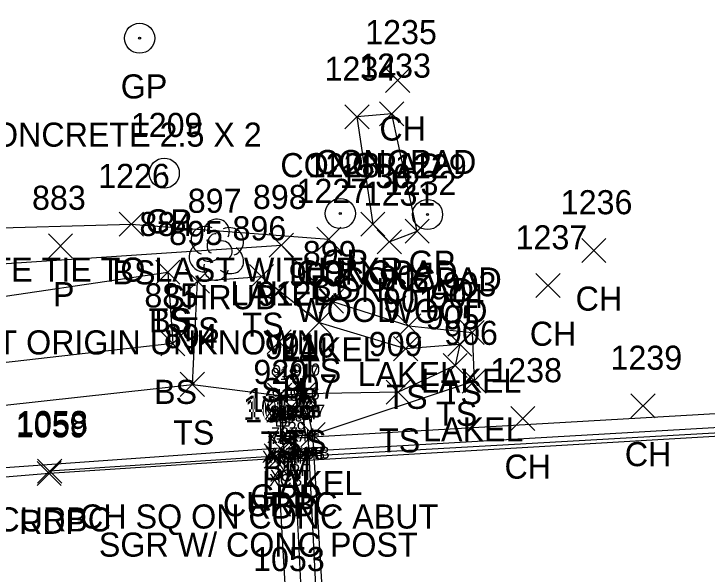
# Model space of a CAD drawing. Extents: x 1716490 to 1717645, y 888034 to 890004.
# Drawn here: x 1716855 to 1716912.5, y 888233.3 to 888279.7 of the extents above; entities that cross this region are included whole.
import ezdxf

# ---------------------------------------------------------------- set-up
doc = ezdxf.new("R2010")
doc.units = 0
for name, color, linetype in [('B_A', 7, 'Continuous'), ('B_I', 7, 'Continuous'), ('B_TIC', 7, 'Continuous'), ('BDC', 7, 'Continuous'), ('BF', 7, 'Continuous'), ('BR', 7, 'Continuous'), ('BSE', 7, 'Continuous'), ('BSUBM', 7, 'Continuous'), ('C_A', 7, 'Continuous'), ('C_C', 7, 'Continuous'), ('C_I', 7, 'Continuous'), ('CPBM', 7, 'Continuous'), ('D_A', 7, 'Continuous'), ('D_C', 7, 'Continuous'), ('D_I', 7, 'Continuous'), ('D_TIC', 7, 'Continuous'), ('L_A', 7, 'Continuous'), ('L_I', 7, 'Continuous'), ('L_TIC', 7, 'Continuous'), ('LAWE', 7, 'Continuous'), ('LELB', 7, 'Continuous'), ('LS', 7, 'Continuous'), ('LSH', 7, 'Continuous'), ('P_A', 7, 'Continuous'), ('P_I', 7, 'Continuous'), ('P_TIC', 7, 'Continuous'), ('PET', 7, 'Continuous'), ('R_A', 7, 'Continuous'), ('R_C', 7, 'Continuous'), ('R_I', 7, 'Continuous'), ('R_TIC', 7, 'Continuous'), ('RC', 7, 'Continuous'), ('RGP', 7, 'Continuous'), ('RGR', 7, 'Continuous')]:
    doc.layers.add(name, color=color, linetype=linetype)

msp = doc.modelspace()

# ---------------------------------------------------------------- linework, layer by layer
at = {"layer": 'B_TIC'}
for p, q in [((1716879.094, 888248.225), (1716879.169, 888248.225)), ((1716877.033, 888248.088), (1716877.108, 888248.088)), ((1716877.197, 888247.861), (1716877.272, 888247.861)), ((1716878.974, 888248.087), (1716879.049, 888248.087)), ((1716877.278, 888246.136), (1716877.354, 888246.136)), ((1716879.046, 888246.236), (1716879.121, 888246.236)), ((1716877.138, 888244.751), (1716877.214, 888244.751)), ((1716877.276, 888244.688), (1716877.351, 888244.688)), ((1716878.173, 888244.72), (1716878.249, 888244.72)), ((1716879.151, 888244.793), (1716879.226, 888244.793)), ((1716879.373, 888244.78), (1716879.449, 888244.78)), ((1716879.797, 888244.823), (1716879.873, 888244.823)), ((1716877.305, 888244.49), (1716877.38, 888244.49)), ((1716877.305, 888244.49), (1716877.38, 888244.49)), ((1716877.965, 888244.411), (1716878.041, 888244.411)), ((1716878.145, 888243.386), (1716878.22, 888243.386)), ((1716877.426, 888242.56), (1716877.502, 888242.56)), ((1716877.5, 888242.928), (1716877.575, 888242.928))]:
    msp.add_line(p, q, dxfattribs=at)
for points in [[(1716879.09, 888247.725), (1716879.09, 888248.725)], [(1716877.029, 888247.588), (1716877.029, 888248.588)], [(1716877.193, 888247.361), (1716877.193, 888248.361)], [(1716878.59, 888248.225), (1716879.59, 888248.225)], [(1716878.97, 888247.587), (1716878.97, 888248.587)], [(1716876.529, 888248.088), (1716877.529, 888248.088)], [(1716876.693, 888247.861), (1716877.693, 888247.861)], [(1716878.47, 888248.087), (1716879.47, 888248.087)], [(1716877.275, 888245.636), (1716877.275, 888246.636)], [(1716879.042, 888245.736), (1716879.042, 888246.736)], [(1716876.775, 888246.136), (1716877.775, 888246.136)], [(1716878.542, 888246.236), (1716879.542, 888246.236)], [(1716877.135, 888244.251), (1716877.135, 888245.251)], [(1716879.147, 888244.292), (1716879.147, 888245.293)], [(1716879.37, 888244.28), (1716879.37, 888245.28)], [(1716879.794, 888244.323), (1716879.794, 888245.323)], [(1716876.635, 888244.751), (1716877.635, 888244.751)], [(1716876.772, 888244.688), (1716877.772, 888244.688)], [(1716877.272, 888244.188), (1716877.272, 888245.188)], [(1716877.301, 888243.99), (1716877.301, 888244.99)], [(1716877.301, 888243.99), (1716877.301, 888244.99)], [(1716877.67, 888244.72), (1716878.67, 888244.72)], [(1716877.962, 888243.911), (1716877.962, 888244.911)], [(1716878.17, 888244.22), (1716878.17, 888245.22)], [(1716878.647, 888244.793), (1716879.647, 888244.793)], [(1716878.87, 888244.78), (1716879.87, 888244.78)], [(1716879.294, 888244.823), (1716880.294, 888244.823)], [(1716876.801, 888244.49), (1716877.801, 888244.49)], [(1716876.801, 888244.49), (1716877.801, 888244.49)], [(1716877.462, 888244.411), (1716878.462, 888244.411)], [(1716878.141, 888242.886), (1716878.141, 888243.886)], [(1716877.423, 888242.06), (1716877.423, 888243.06)], [(1716877.496, 888242.428), (1716877.496, 888243.428)], [(1716877.641, 888243.386), (1716878.641, 888243.386)], [(1716876.923, 888242.56), (1716877.923, 888242.56)], [(1716876.996, 888242.928), (1716877.996, 888242.928)]]:
    msp.add_lwpolyline(points, dxfattribs=at)
at = {"layer": 'BDC'}
for points in [[(1717176.589, 888262.234), (1717176.877, 888260.812), (1717116.829, 888257.088), (1717056.7, 888253.344), (1716997.03, 888249.858), (1716936.998, 888246.313), (1716877.496, 888242.928), (1716877.301, 888244.49)], [(1717176.976, 888262.024), (1717176.866, 888260.514), (1717116.827, 888256.946), (1717056.83, 888253.148), (1716997.002, 888249.663), (1716937.062, 888246.095), (1716877.423, 888242.56)]]:
    msp.add_lwpolyline(points, dxfattribs=at)
at = {"layer": 'BF'}
msp.add_lwpolyline([(1717176.589, 888262.234), (1717116.538, 888258.636), (1717056.61, 888254.944), (1716996.925, 888251.433), (1716937.102, 888247.945), (1716877.301, 888244.49)], dxfattribs=at)
at = {"layer": 'BR'}
msp.add_lwpolyline([(1717175.997, 888261.982), (1717175.88, 888261.141), (1717117.062, 888257.612), (1717056.557, 888253.997), (1716997.021, 888250.409), (1716936.966, 888246.784), (1716878.141, 888243.386), (1716877.962, 888244.411)], dxfattribs=at)
at = {"layer": 'BSE'}
for points in [[(1716879.79, 888212.64), (1716878.17, 888244.72)], [(1716879.37, 888244.78), (1716880.99, 888212.7)]]:
    msp.add_lwpolyline(points, dxfattribs=at)
at = {"layer": 'BSUBM'}
for points in [[(1716879.794, 888244.823), (1716879.09, 888248.225), (1716877.029, 888248.088), (1716877.135, 888244.751)], [(1716877.272, 888244.688), (1716879.147, 888244.793), (1716879.042, 888246.236), (1716878.97, 888248.087), (1716877.193, 888247.861), (1716877.275, 888246.136)], [(1716877.275, 888246.136), (1716877.272, 888244.688)], [(1716881.978, 888209.102), (1716879.794, 888244.823)]]:
    msp.add_lwpolyline(points, dxfattribs=at)
at = {"layer": 'CPBM'}
for p, q in [((1716876.798, 888245.534), (1716876.798, 888246.534)), ((1716876.798, 888246.534), (1716877.798, 888246.534)), ((1716877.798, 888246.534), (1716877.798, 888245.534)), ((1716877.3, 888246.035), (1716877.3, 888246.035)), ((1716877.3, 888246.035), (1716877.3, 888246.035)), ((1716877.798, 888245.534), (1716876.798, 888245.534))]:
    msp.add_line(p, q, dxfattribs=at)
at = {"layer": 'D_TIC'}
for points in [[(1716857.85, 888259.48), (1716859.85, 888261.48)], [(1716859.85, 888259.48), (1716857.85, 888261.48)]]:
    msp.add_lwpolyline(points, dxfattribs=at)
at = {"layer": 'L_TIC'}
for points in [[(1716885.819, 888273.226), (1716887.819, 888275.226)], [(1716887.819, 888273.226), (1716885.819, 888275.226)], [(1716885.327, 888270.447), (1716887.327, 888272.447)], [(1716887.327, 888270.447), (1716885.327, 888272.447)], [(1716882.446, 888270.19), (1716884.446, 888272.19)], [(1716884.446, 888270.19), (1716882.446, 888272.19)], [(1716863.723, 888261.295), (1716865.723, 888263.295)], [(1716865.723, 888261.295), (1716863.723, 888263.295)], [(1716883.769, 888261.285), (1716885.769, 888263.285)], [(1716885.769, 888261.285), (1716883.769, 888263.285)], [(1716887.438, 888260.705), (1716889.438, 888262.705)], [(1716889.438, 888260.705), (1716887.438, 888262.705)], [(1716880.119, 888260.054), (1716882.119, 888262.054)], [(1716882.119, 888260.054), (1716880.119, 888262.054)], [(1716876.174, 888259.555), (1716878.174, 888261.555)], [(1716878.174, 888259.555), (1716876.174, 888261.555)], [(1716885.128, 888259.824), (1716887.128, 888261.824)], [(1716887.128, 888259.824), (1716885.128, 888261.824)], [(1716902.097, 888259.113), (1716904.097, 888261.113)], [(1716904.097, 888259.113), (1716902.097, 888261.113)], [(1716866.758, 888257.309), (1716868.758, 888259.309)], [(1716868.758, 888257.309), (1716866.758, 888259.309)], [(1716866.758, 888257.309), (1716868.758, 888259.309)], [(1716868.758, 888257.309), (1716866.758, 888259.309)], [(1716869.22, 888256.561), (1716871.22, 888258.561)], [(1716871.22, 888256.561), (1716869.22, 888258.561)], [(1716874.534, 888256.948), (1716876.534, 888258.948)], [(1716876.534, 888256.948), (1716874.534, 888258.948)], [(1716898.296, 888256.2), (1716900.296, 888258.2)], [(1716900.296, 888256.2), (1716898.296, 888258.2)], [(1716880.322, 888254.897), (1716882.322, 888256.897)], [(1716882.322, 888254.897), (1716880.322, 888256.897)], [(1716879.311, 888253.139), (1716881.311, 888255.139)], [(1716881.311, 888253.139), (1716879.311, 888255.139)], [(1716886.736, 888252.856), (1716888.736, 888254.856)], [(1716888.736, 888252.856), (1716886.736, 888254.856)], [(1716891.995, 888252.305), (1716893.995, 888254.305)], [(1716893.995, 888252.305), (1716891.995, 888254.305)], [(1716867.17, 888251.377), (1716869.17, 888253.377)], [(1716869.17, 888251.377), (1716867.17, 888253.377)], [(1716875.994, 888251.519), (1716877.994, 888253.519)], [(1716877.994, 888251.519), (1716875.994, 888253.519)], [(1716890.986, 888251.334), (1716892.986, 888253.334)], [(1716892.986, 888251.334), (1716890.986, 888253.334)], [(1716886.482, 888250.965), (1716888.482, 888252.965)], [(1716888.482, 888250.965), (1716886.482, 888252.965)], [(1716890.594, 888249.562), (1716892.594, 888251.562)], [(1716892.594, 888249.562), (1716890.594, 888251.562)], [(1716868.789, 888248.001), (1716870.789, 888250.001)], [(1716870.789, 888248.001), (1716868.789, 888250.001)], [(1716868.789, 888248.001), (1716870.789, 888250.001)], [(1716870.789, 888248.001), (1716868.789, 888250.001)], [(1716892.169, 888248.274), (1716894.169, 888250.274)], [(1716894.169, 888248.274), (1716892.169, 888250.274)], [(1716885.869, 888247.35), (1716887.869, 888249.35)], [(1716887.869, 888247.35), (1716885.869, 888249.35)], [(1716876.029, 888247.088), (1716878.029, 888249.088)], [(1716878.029, 888247.088), (1716876.029, 888249.088)], [(1716878.09, 888247.225), (1716880.09, 888249.225)], [(1716880.09, 888247.225), (1716878.09, 888249.225)], [(1716906.178, 888246.209), (1716908.178, 888248.209)], [(1716908.178, 888246.209), (1716906.178, 888248.209)], [(1716896.198, 888245.174), (1716898.198, 888247.174)], [(1716898.198, 888245.174), (1716896.198, 888247.174)], [(1716878.794, 888243.823), (1716880.794, 888245.823)], [(1716880.794, 888243.823), (1716878.794, 888245.823)]]:
    msp.add_lwpolyline(points, dxfattribs=at)
at = {"layer": 'LAWE'}
msp.add_lwpolyline([(1716792.923, 888333.593), (1716808.09, 888324.58), (1716820.08, 888290.735), (1716820.719, 888281.539), (1716822.371, 888277.267), (1716826.189, 888277.556), (1716826.504, 888273.884), (1716836.716, 888265.482), (1716850.622, 888258.774), (1716877.174, 888260.555), (1716881.322, 888255.897), (1716887.736, 888253.856), (1716892.995, 888253.305), (1716893.169, 888249.274), (1716879.794, 888244.823)], dxfattribs=at)
at = {"layer": 'LELB'}
for points in [[(1716798.784, 888338.684), (1716807.198, 888328.202), (1716816.689, 888310.638), (1716822.622, 888293.629), (1716826.404, 888294.991), (1716827.92, 888291.14), (1716823.715, 888289.67), (1716822.512, 888293.041), (1716821.152, 888288.315), (1716833.507, 888272.565), (1716850.988, 888261.906), (1716864.723, 888262.295), (1716881.119, 888261.054)], [(1716791.288, 888331.615), (1716796.122, 888325.707), (1716805.751, 888321.457), (1716813.357, 888291.514), (1716815.908, 888278.599), (1716830.764, 888256.002), (1716850.124, 888255.716), (1716867.758, 888258.309)], [(1716831.352, 888253.697), (1716835.782, 888246.432), (1716841.647, 888245.886), (1716850.938, 888246.905), (1716869.789, 888249.001), (1716870.22, 888257.561), (1716875.534, 888257.948), (1716880.311, 888254.139), (1716887.482, 888251.965), (1716891.986, 888252.334), (1716891.594, 888250.562), (1716886.869, 888248.35), (1716879.09, 888248.225)], [(1716867.758, 888258.309), (1716868.17, 888252.377), (1716837.365, 888248.868), (1716835.782, 888246.432)], [(1716869.789, 888249.001), (1716877.029, 888248.088)]]:
    msp.add_lwpolyline(points, dxfattribs=at)
at = {"layer": 'LS'}
for points in [[(1716884.769, 888262.285), (1716886.128, 888260.824), (1716888.438, 888261.705), (1716886.327, 888271.447), (1716883.446, 888271.19)], [(1716883.446, 888271.19), (1716884.769, 888262.285)]]:
    msp.add_lwpolyline(points, dxfattribs=at)
at = {"layer": 'LSH'}
msp.add_line((1716871.768, 888260.233), (1716871.768, 888260.233), dxfattribs=at)
msp.add_line((1716871.768, 888260.233), (1716871.768, 888260.233), dxfattribs=at)
msp.add_arc((1716871.815, 888261.667), 1.047, 335.52715, 180.95627, dxfattribs=at)
for centre, major_axis, ratio, start_param, end_param in [((1716870.976, 888260.9), (1.21, -0.512), 0.895232, 1.570796, 4.712389), ((1716872.81, 888260.817), (-1.141, -0.483), 0.949671, 1.570796, 4.712389), ((1716871.56, 888260.692), (-0.208, -0.792), 0.645439, 3.141593, 6.283185), ((1716872.268, 888260.067), (-0.5, 0.667), 0.989748, 3.141593, 6.283185), ((1716870.685, 888259.525), (0.584, -1.042), 0.959034, 3.141593, 6.283185), ((1716872.768, 888259.4), (-1.09, 0.792), 0.841452, 1.570796, 4.712389), ((1716871.31, 888259.483), (-0.625, -0.083), 0.423636, 0, 3.141593), ((1716871.768, 888258.733), (0.265, 1.061), 0.942809, 1.570796, 4.712389)]:
    msp.add_ellipse(centre, major_axis=major_axis, ratio=ratio, start_param=start_param, end_param=end_param, dxfattribs=at)
at = {"layer": 'P_TIC'}
for points in [[(1716875.883, 888241.851), (1716877.883, 888243.851)], [(1716877.883, 888241.851), (1716875.883, 888243.851)], [(1716856.915, 888240.594), (1716858.915, 888242.594)], [(1716858.915, 888240.594), (1716856.915, 888242.594)]]:
    msp.add_lwpolyline(points, dxfattribs=at)
at = {"layer": 'PET'}
msp.add_lwpolyline([(1716669.133, 888208.315), (1716709.505, 888208.714), (1716740.373, 888211.068), (1716775.556, 888211.777), (1716802.021, 888213.013), (1716840.455, 888216.113), (1716878.657, 888218.974), (1716877.597, 888230.504), (1716876.883, 888242.851), (1716857.915, 888241.594), (1716836.634, 888239.831), (1716814.633, 888240.145), (1716785.061, 888241.323), (1716771.928, 888239.872), (1716746.815, 888241.658), (1716719.438, 888242.78), (1716699.752, 888242.907), (1716680.829, 888242.531), (1716671.322, 888244.592)], dxfattribs=at)
at = {"layer": 'R_TIC'}
for points in [[(1716876.112, 888242.702), (1716878.112, 888244.702)], [(1716878.112, 888242.702), (1716876.112, 888244.702)], [(1716875.747, 888242.054), (1716877.747, 888244.054)], [(1716877.747, 888242.054), (1716875.747, 888244.054)], [(1716856.951, 888240.793), (1716858.951, 888242.793)], [(1716858.951, 888240.793), (1716856.951, 888242.793)]]:
    msp.add_lwpolyline(points, dxfattribs=at)
at = {"layer": 'RC'}
msp.add_lwpolyline([(1716876.747, 888243.054), (1716857.951, 888241.793)], dxfattribs=at)
at = {"layer": 'RGP'}
for p, q in [((1716865.415, 888277.72), (1716865.415, 888277.72)), ((1716867.457, 888266.523), (1716867.457, 888266.523)), ((1716882.065, 888263.174), (1716882.065, 888263.174)), ((1716889.301, 888263.092), (1716889.301, 888263.092))]:
    msp.add_line(p, q, dxfattribs=at)
for centre, radius in [((1716865.415, 888277.72), 1.25), ((1716865.415, 888277.72), 0.0833), ((1716867.457, 888266.523), 1.25), ((1716867.457, 888266.523), 0.0833), ((1716882.065, 888263.174), 1.25), ((1716889.301, 888263.092), 1.25), ((1716882.065, 888263.174), 0.0833), ((1716889.301, 888263.092), 0.0833)]:
    msp.add_circle(centre, radius, dxfattribs=at)
at = {"layer": 'RGR'}
msp.add_lwpolyline([(1716877.112, 888243.702), (1716838.37, 888240.943)], dxfattribs=at)

# ---------------------------------------------------------------- texts
at = {"layer": 'B_A'}
for s, p in [('XAB', (1716875.75, 888246.088)), ('XAT', (1716877.675, 888246.087)), ('XAB', (1716877.811, 888246.225)), ('XAT', (1716875.898, 888245.861)), ('XAT', (1716875.979, 888244.136)), ('XAT', (1716877.747, 888244.236)), ('XAB', (1716875.855, 888242.751)), ('XAT', (1716875.977, 888242.688)), ('XBS', (1716876.91, 888242.72)), ('XAT', (1716877.852, 888242.793)), ('XBS', (1716878.11, 888242.78)), ('XAB', (1716878.514, 888242.823)), ('XFAT', (1716875.557, 888242.49)), ('XCT', (1716876.022, 888242.49)), ('XRF', (1716876.722, 888242.411)), ('XRF', (1716876.901, 888241.386)), ('XCT', (1716876.217, 888240.928)), ('XCB', (1716876.159, 888240.56))]:
    msp.add_text(s, height=1, dxfattribs=at).set_placement(p)
at = {"layer": 'B_I'}
for s, p in [('911', (1716876.415, 888249.588)), ('917', (1716878.073, 888249.587)), ('910', (1716878.149, 888249.725)), ('918', (1716876.295, 888249.361)), ('916', (1716878.117, 888247.736)), ('919', (1716876.373, 888247.636)), ('728', (1716876.12, 888245.99)), ('728', (1716876.12, 888245.99)), ('913', (1716876.237, 888246.251)), ('914', (1716876.375, 888246.188)), ('1382', (1716876.824, 888246.22)), ('908', (1716878.15, 888246.28)), ('915', (1716878.249, 888246.293)), ('907', (1716878.573, 888246.323)), ('730', (1716876.737, 888245.911)), ('729', (1716876.956, 888244.886)), ('727', (1716876.315, 888244.428)), ('726', (1716876.214, 888244.06))]:
    msp.add_text(s, height=1, dxfattribs=at).set_placement(p)
at = {"layer": 'C_A'}
msp.add_text('BM', height=2, dxfattribs=at).set_placement((1716875.615, 888241.035))
at = {"layer": 'C_C'}
msp.add_text('CH SQ ON CONC ABUT', height=2, dxfattribs=at).set_placement((1716860.474, 888237.035))
at = {"layer": 'C_I'}
msp.add_text('920', height=2, dxfattribs=at).set_placement((1716874.852, 888249.035))
at = {"layer": 'D_A'}
msp.add_text('P', height=2, dxfattribs=at).set_placement((1716858.227, 888255.48))
at = {"layer": 'D_C'}
msp.add_text('8 CGMP OUTLET ORIGIN UNKNOWN', height=2, dxfattribs=at).set_placement((1716833.708, 888251.48))
at = {"layer": 'D_I'}
msp.add_text('883', height=2, dxfattribs=at).set_placement((1716856.487, 888263.48))
at = {"layer": 'L_A'}
for s, p in [('CH', (1716885.307, 888269.226)), ('CONCPAD', (1716879.973, 888266.447)), ('CONCPAD', (1716877.092, 888266.19)), ('BS', (1716863.164, 888257.295)), ('CONCPAD', (1716878.415, 888257.285)), ('CONCPAD', (1716882.083, 888256.705)), ('BS', (1716879.56, 888256.054)), ('LAKEL', (1716872.938, 888255.555)), ('CONCPAD', (1716879.774, 888255.824)), ('SHRUB', (1716867.398, 888255.233)), ('CH', (1716901.585, 888255.113)), ('TS', (1716866.168, 888253.309)), ('BS', (1716866.199, 888253.309)), ('TS', (1716868.629, 888252.561)), ('TS', (1716873.944, 888252.948)), ('CH', (1716897.784, 888252.2)), ('LAKEL', (1716877.086, 888250.897)), ('TS', (1716878.721, 888249.139)), ('LAKEL', (1716883.5, 888248.856)), ('LAKEL', (1716888.759, 888248.305)), ('BS', (1716866.611, 888247.377)), ('SH', (1716875.482, 888247.519)), ('TS', (1716890.395, 888247.334)), ('TS', (1716885.891, 888246.965)), ('TS', (1716890.004, 888245.562)), ('TS', (1716868.198, 888244.001)), ('TS', (1716868.198, 888244.001)), ('LAKEL', (1716888.932, 888244.274)), ('TS', (1716877.5, 888243.225)), ('TS', (1716885.278, 888243.35)), ('TS', (1716875.439, 888243.088)), ('CH', (1716905.666, 888242.209)), ('CH', (1716895.686, 888241.174)), ('LAKEL', (1716875.558, 888239.823))]:
    msp.add_text(s, height=2, dxfattribs=at).set_placement(p)
at = {"layer": 'L_I'}
for s, p in [('1235', (1716884.126, 888277.226)), ('1233', (1716883.634, 888274.447)), ('1234', (1716880.753, 888274.19)), ('1226', (1716861.975, 888265.295)), ('1230', (1716881.989, 888265.285)), ('1232', (1716885.745, 888264.705)), ('1227', (1716878.426, 888264.054)), ('898', (1716874.812, 888263.555)), ('1231', (1716884.002, 888263.824)), ('897', (1716869.406, 888263.233)), ('1236', (1716900.349, 888263.113)), ('884', (1716865.396, 888261.309)), ('884', (1716865.396, 888261.309)), ('895', (1716867.858, 888260.561)), ('896', (1716873.117, 888260.948)), ('1237', (1716896.603, 888260.2)), ('899', (1716878.952, 888258.897)), ('900', (1716877.783, 888257.139)), ('902', (1716885.295, 888256.856)), ('903', (1716890.554, 888256.305)), ('885', (1716865.808, 888255.377)), ('912', (1716875.199, 888255.519)), ('904', (1716889.545, 888255.334)), ('901', (1716885.608, 888254.965)), ('905', (1716889.153, 888253.562)), ('894', (1716867.427, 888252.001)), ('894', (1716867.427, 888252.001)), ('906', (1716890.673, 888252.274)), ('909', (1716884.42, 888251.35)), ('911', (1716875.801, 888251.088)), ('910', (1716877.208, 888251.225)), ('1239', (1716904.477, 888250.209)), ('1238', (1716894.505, 888249.174)), ('907', (1716877.353, 888247.823))]:
    msp.add_text(s, height=2, dxfattribs=at).set_placement(p)
at = {"layer": 'P_A'}
for p in [(1716874.371, 888237.851), (1716855.403, 888236.594)]:
    msp.add_text('RDP', height=2, dxfattribs=at).set_placement(p)
at = {"layer": 'P_I'}
for s, p in [('1054', (1716874.111, 888245.851)), ('1059', (1716855.135, 888244.594)), ('1053', (1716874.825, 888233.504)), ('1053', (1716874.825, 888233.504))]:
    msp.add_text(s, height=2, dxfattribs=at).set_placement(p)
at = {"layer": 'R_A'}
for s, p in [('GP', (1716863.848, 888272.72)), ('GP', (1716865.89, 888261.523)), ('GP', (1716880.498, 888258.174)), ('GP', (1716887.734, 888258.092)), ('GRR', (1716874.6, 888238.702)), ('CURBC', (1716872.33, 888238.054)), ('CURBC', (1716853.534, 888236.793))]:
    msp.add_text(s, height=2, dxfattribs=at).set_placement(p)
at = {"layer": 'R_C'}
for s, p in [('CONCRETE 2.5 X 2', (1716851.32, 888268.72)), ('CONCRETE TIE TO LAST WITH RXR', (1716841.527, 888257.523)), ('WOOD', (1716878.42, 888254.174)), ('WOOD', (1716885.656, 888254.092)), ('SGR W/ CONC POST', (1716862.033, 888234.702))]:
    msp.add_text(s, height=2, dxfattribs=at).set_placement(p)
at = {"layer": 'R_I'}
for s, p in [('1209', (1716864.677, 888269.523)), ('1228', (1716879.372, 888266.174)), ('1229', (1716886.601, 888266.092)), ('1056', (1716874.285, 888246.702)), ('1055', (1716873.976, 888246.054)), ('1058', (1716855.179, 888244.793))]:
    msp.add_text(s, height=2, dxfattribs=at).set_placement(p)

doc.saveas('drawing.dxf')
